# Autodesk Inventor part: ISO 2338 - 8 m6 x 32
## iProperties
Created: 2008-08
Part Number: ISO 2338 - 8 m6 x 32
Material: BgAAAEgAAABOAEEATQBFAFMACgBNAGEAdABlAHIAaQBhAGwAcwAKADEAOgBTAHQAZQBlAGwALAAgAE0AaQBsAGQACgAKAEUATgBEAAoAAAA=
Description: Zylinderstift
Vendor: Autodesk Inc.
Document SubType Name: Modeling
Standard: ISO 2338
Designer: U.Rapp
Standards Organization: DIN
Language: de-DE
Size Designation: 8 m6 x 32
Categories: <MemberInstance Version="R10.0.0"><Categories><Category DisplayName="Schrauben" InternalName="e4da775c-781d-43d5-af7c-5136215cf5a6" Mnemonic="FSTN"><Category Di
Author: U.Rapp
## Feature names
1. Körper [Extrusion]
2. Fase1 [Chamfer]
3. Skizze2 [Chamfer]
